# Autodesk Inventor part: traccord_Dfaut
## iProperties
Created: 2007-07
Part Number: traccord_Dfaut
Document SubType Name: Modeling
Designer: EF
Density: 1 g/cm^3
Author: EF
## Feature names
1. Base1
